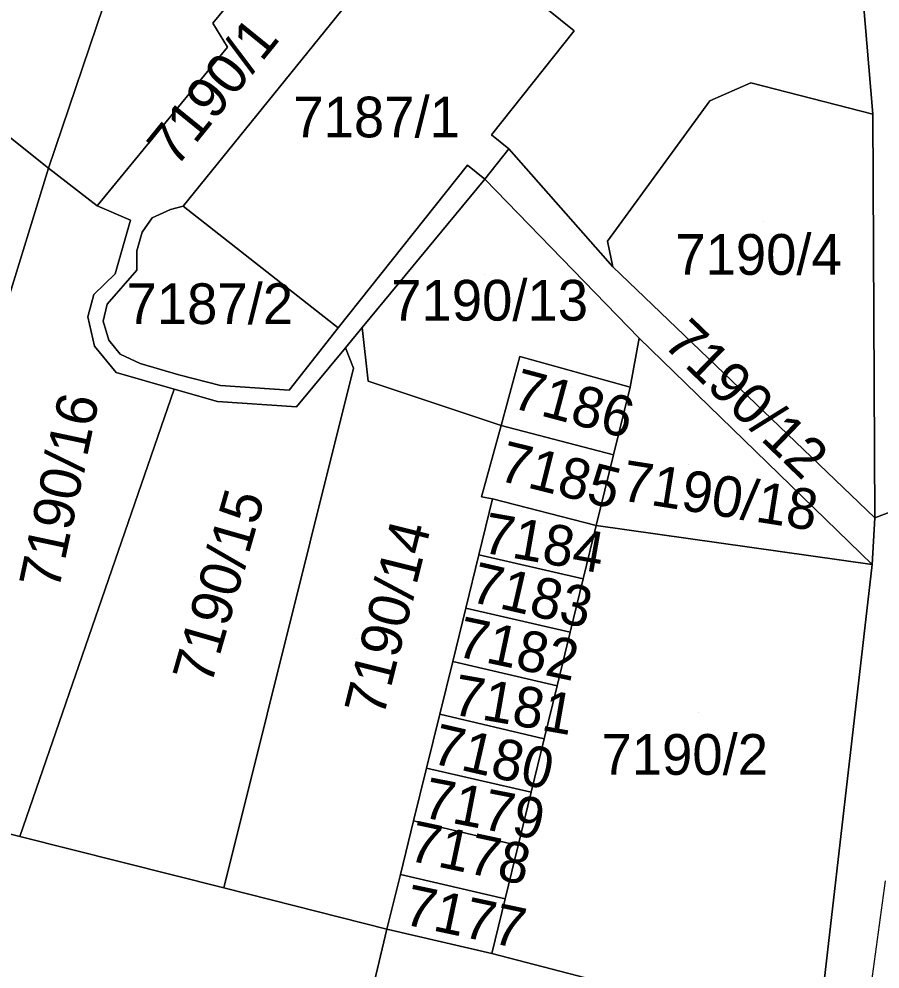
# Model space of a CAD drawing. Extents: x -266199 to -261993, y -1239047 to -1235108.
# Drawn here: x -263537.93 to -263495.63, y -1236309.89 to -1236263.23 of the extents above; entities that cross this region are included whole.
import ezdxf

# ---------------------------------------------------------------- set-up
doc = ezdxf.new("R2010")
doc.units = 0
for name, color, linetype in [('body_kn', 7, 'Continuous'), ('kladpar_druhypozemkov', 7, 'Continuous'), ('kladpar_hranice', 7, 'Continuous'), ('kladpar_parcelnecisla', 7, 'Continuous'), ('kladpar_plochy', 7, 'Continuous'), ('zappar_hrandruhpozemk', 7, 'Continuous')]:
    doc.layers.add(name, color=color, linetype=linetype)

msp = doc.modelspace()

# ---------------------------------------------------------------- linework, layer by layer
at = {"layer": 'body_kn'}
for p, q in [((-263528.41, -1236263.43), (-263528.41, -1236263.43)), ((-263510.66, -1236263.8), (-263510.66, -1236263.8)), ((-263510.66, -1236263.8), (-263510.66, -1236263.8)), ((-263527.69, -1236264.61), (-263527.69, -1236264.61)), ((-263501.98, -1236266.36), (-263501.98, -1236266.36)), ((-263503.99, -1236267.25), (-263503.99, -1236267.25)), ((-263495.99, -1236267.9), (-263495.99, -1236267.9)), ((-263514.72, -1236268.91), (-263514.72, -1236268.91)), ((-263513.86, -1236269.6), (-263513.86, -1236269.6)), ((-263536.48, -1236270.56), (-263536.48, -1236270.56)), ((-263536.48, -1236270.56), (-263536.48, -1236270.56)), ((-263515.9, -1236270.4), (-263515.9, -1236270.4)), ((-263515.04, -1236271.09), (-263515.04, -1236271.09)), ((-263515.04, -1236271.09), (-263515.04, -1236271.09)), ((-263534.09, -1236272.4), (-263534.09, -1236272.4)), ((-263534.09, -1236272.4), (-263534.09, -1236272.4)), ((-263529.86, -1236272.42), (-263529.86, -1236272.42)), ((-263529.86, -1236272.42), (-263529.86, -1236272.42)), ((-263530.49, -1236272.59), (-263530.49, -1236272.59)), ((-263530.49, -1236272.59), (-263530.49, -1236272.59)), ((-263532.45, -1236273.11), (-263532.45, -1236273.11)), ((-263531.39, -1236272.99), (-263531.39, -1236272.99)), ((-263531.87, -1236273.69), (-263531.87, -1236273.69)), ((-263509.02, -1236274.13), (-263509.02, -1236274.13)), ((-263532.14, -1236274.62), (-263532.14, -1236274.62)), ((-263533.2, -1236275.75), (-263533.2, -1236275.75)), ((-263532.14, -1236275.56), (-263532.14, -1236275.56)), ((-263508.76, -1236275.4), (-263508.76, -1236275.4)), ((-263534.25, -1236276.75), (-263534.25, -1236276.75)), ((-263533.6, -1236277.24), (-263533.6, -1236277.24)), ((-263534.55, -1236277.86), (-263534.55, -1236277.86)), ((-263533.79, -1236278.07), (-263533.79, -1236278.07)), ((-263522.24, -1236278.4), (-263522.24, -1236278.4)), ((-263521.07, -1236278.38), (-263521.07, -1236278.38)), ((-263521.07, -1236278.38), (-263521.07, -1236278.38)), ((-263533.52, -1236279), (-263533.52, -1236279)), ((-263507.46, -1236278.91), (-263507.46, -1236278.91)), ((-263534.22, -1236279.3), (-263534.22, -1236279.3)), ((-263521.89, -1236279.37), (-263521.89, -1236279.37)), ((-263521.89, -1236279.37), (-263521.89, -1236279.37)), ((-263532.95, -1236279.69), (-263532.95, -1236279.69)), ((-263513.32, -1236279.8), (-263513.32, -1236279.8)), ((-263531.98, -1236280.14), (-263531.98, -1236280.14)), ((-263521.49, -1236280.38), (-263521.49, -1236280.38)), ((-263533.15, -1236280.59), (-263533.15, -1236280.59)), ((-263530.08, -1236280.71), (-263530.08, -1236280.71)), ((-263528.02, -1236281.22), (-263528.02, -1236281.22)), ((-263520.77, -1236281.02), (-263520.77, -1236281.02)), ((-263507.91, -1236281.31), (-263507.91, -1236281.31)), ((-263530.31, -1236281.4), (-263530.31, -1236281.4)), ((-263530.31, -1236281.4), (-263530.31, -1236281.4)), ((-263524.66, -1236281.45), (-263524.66, -1236281.45)), ((-263528.17, -1236282.01), (-263528.17, -1236282.01)), ((-263524.3, -1236282.28), (-263524.3, -1236282.28)), ((-263514.24, -1236283.19), (-263514.24, -1236283.19)), ((-263514.24, -1236283.19), (-263514.24, -1236283.19)), ((-263508.72, -1236284.64), (-263508.72, -1236284.64)), ((-263515.2, -1236286.69), (-263515.2, -1236286.69)), ((-263514.66, -1236286.8), (-263514.66, -1236286.8)), ((-263514.66, -1236286.8), (-263514.66, -1236286.8)), ((-263495.88, -1236287.73), (-263495.88, -1236287.73)), ((-263495.88, -1236287.73), (-263495.88, -1236287.73)), ((-263509.57, -1236288.11), (-263509.57, -1236288.11)), ((-263509.57, -1236288.11), (-263509.57, -1236288.11)), ((-263515.33, -1236289.55), (-263515.33, -1236289.55)), ((-263515.33, -1236289.55), (-263515.33, -1236289.55)), ((-263496.02, -1236290.02), (-263496.02, -1236290.02)), ((-263496.02, -1236290.02), (-263496.02, -1236290.02)), ((-263510.21, -1236290.73), (-263510.21, -1236290.73)), ((-263515.98, -1236292.17), (-263515.98, -1236292.17)), ((-263515.98, -1236292.17), (-263515.98, -1236292.17)), ((-263510.85, -1236293.35), (-263510.85, -1236293.35)), ((-263516.62, -1236294.79), (-263516.62, -1236294.79)), ((-263516.62, -1236294.79), (-263516.62, -1236294.79)), ((-263511.49, -1236295.98), (-263511.49, -1236295.98)), ((-263517.26, -1236297.38), (-263517.26, -1236297.38)), ((-263517.26, -1236297.38), (-263517.26, -1236297.38)), ((-263512.13, -1236298.59), (-263512.13, -1236298.59)), ((-263517.91, -1236300.02), (-263517.91, -1236300.02)), ((-263517.91, -1236300.02), (-263517.91, -1236300.02)), ((-263512.77, -1236301.21), (-263512.77, -1236301.21)), ((-263518.55, -1236302.62), (-263518.55, -1236302.62)), ((-263518.55, -1236302.62), (-263518.55, -1236302.62)), ((-263537.88, -1236303.38), (-263537.88, -1236303.38)), ((-263513.4, -1236303.82), (-263513.4, -1236303.82)), ((-263519.19, -1236305.25), (-263519.19, -1236305.25)), ((-263519.19, -1236305.25), (-263519.19, -1236305.25)), ((-263527.86, -1236305.91), (-263527.86, -1236305.91)), ((-263514.04, -1236306.44), (-263514.04, -1236306.44)), ((-263519.85, -1236307.93), (-263519.85, -1236307.93)), ((-263519.85, -1236307.93), (-263519.85, -1236307.93)), ((-263514.7, -1236309.13), (-263514.7, -1236309.13))]:
    msp.add_line(p, q, dxfattribs=at)
at = {"layer": 'kladpar_druhypozemkov'}
for p, q in [((-263520.11, -1236266.95), (-263520.11, -1236266.95)), ((-263501.37, -1236273.19), (-263501.37, -1236273.19)), ((-263515.04, -1236275.78), (-263515.04, -1236275.78)), ((-263529.42, -1236276.34), (-263529.42, -1236276.34)), ((-263508.05, -1236277.86), (-263508.05, -1236277.86)), ((-263510.77, -1236281.31), (-263510.77, -1236281.31)), ((-263511.72, -1236284.66), (-263511.72, -1236284.66)), ((-263505.03, -1236285.12), (-263505.03, -1236285.12)), ((-263512.31, -1236288.01), (-263512.31, -1236288.01)), ((-263529.29, -1236290.6), (-263529.29, -1236290.6)), ((-263512.99, -1236290.59), (-263512.99, -1236290.59)), ((-263513.94, -1236293.24), (-263513.94, -1236293.24)), ((-263521.37, -1236293.68), (-263521.37, -1236293.68)), ((-263514.07, -1236295.96), (-263514.07, -1236295.96)), ((-263504.53, -1236297.27), (-263504.53, -1236297.27)), ((-263515.02, -1236298.4), (-263515.02, -1236298.4)), ((-263515.43, -1236301.12), (-263515.43, -1236301.12)), ((-263515.97, -1236303.7), (-263515.97, -1236303.7)), ((-263516.44, -1236306.35), (-263516.44, -1236306.35))]:
    msp.add_line(p, q, dxfattribs=at)
at = {"layer": 'kladpar_hranice'}
for p, q in [((-263509.57, -1236288.11), (-263496.02, -1236290.02)), ((-263496.02, -1236290.02), (-263509.57, -1236288.11))]:
    msp.add_line(p, q, dxfattribs=at)
for points in [[(-263539.64, -1236251.93), (-263532.02, -1236257.4), (-263532.77, -1236259.62), (-263536.48, -1236270.56), (-263556.07, -1236254.9), (-263558.35, -1236253.65), (-263553.41, -1236240.69), (-263550.2, -1236243.03), (-263549.33, -1236243.77), (-263552.3, -1236247.3), (-263550.89, -1236248.39), (-263551.92, -1236249.71), (-263550.96, -1236250.5), (-263553.07, -1236253.02), (-263546.88, -1236258.21), (-263544.72, -1236255.63), (-263543.56, -1236256.61), (-263539.64, -1236251.93)], [(-263510.66, -1236263.8), (-263512.67, -1236262.17), (-263502.28, -1236249.13), (-263499.14, -1236245.39), (-263497.67, -1236252.96), (-263496.66, -1236259.95), (-263495.99, -1236267.9), (-263501.98, -1236266.36), (-263503.99, -1236267.25), (-263509.02, -1236274.13), (-263508.76, -1236275.4), (-263513.86, -1236269.6), (-263514.72, -1236268.91), (-263510.66, -1236263.8)], [(-263534.09, -1236272.4), (-263536.48, -1236270.56), (-263532.77, -1236259.62), (-263532.02, -1236257.4), (-263531.64, -1236257.68), (-263527.4, -1236251.24), (-263521.65, -1236255.27), (-263524.98, -1236259.27), (-263528.41, -1236263.43), (-263527.69, -1236264.61), (-263534.09, -1236272.4)], [(-263536.48, -1236270.56), (-263540.55, -1236283.75), (-263552.05, -1236274.37), (-263547.85, -1236269.28), (-263547.02, -1236270), (-263544.76, -1236267.39), (-263549.56, -1236263.34), (-263552.02, -1236266.32), (-263554.1, -1236264.62), (-263555.1, -1236265.84), (-263556.51, -1236264.69), (-263559.5, -1236268.37), (-263562.84, -1236265.41), (-263558.35, -1236253.65), (-263556.07, -1236254.9), (-263536.48, -1236270.56)], [(-263477.77, -1236255.09), (-263476.89, -1236265.26), (-263476.37, -1236281.32), (-263478.43, -1236281.04), (-263490.86, -1236285.81), (-263494.12, -1236287.05), (-263495.88, -1236287.73), (-263495.99, -1236267.9), (-263496.66, -1236259.95)], [(-263529.86, -1236272.42), (-263521.51, -1236262.08), (-263518.11, -1236257.87), (-263512.67, -1236262.17), (-263510.66, -1236263.8), (-263514.72, -1236268.91), (-263513.86, -1236269.6), (-263515.04, -1236271.09), (-263515.9, -1236270.4), (-263522.24, -1236278.4), (-263529.86, -1236272.42)], [(-263529.86, -1236272.42), (-263530.49, -1236272.59), (-263531.39, -1236272.99), (-263531.87, -1236273.69), (-263532.14, -1236274.62), (-263532.14, -1236275.56), (-263533.6, -1236277.24), (-263533.79, -1236278.07), (-263533.52, -1236279), (-263532.95, -1236279.69), (-263531.98, -1236280.14), (-263530.08, -1236280.71), (-263528.02, -1236281.22), (-263524.66, -1236281.45), (-263522.24, -1236278.4), (-263515.9, -1236270.4), (-263515.04, -1236271.09), (-263521.07, -1236278.38), (-263521.89, -1236279.37), (-263524.3, -1236282.28), (-263528.17, -1236282.01), (-263530.31, -1236281.4), (-263533.15, -1236280.59), (-263534.22, -1236279.3), (-263534.55, -1236277.86), (-263534.25, -1236276.75), (-263533.2, -1236275.75), (-263532.45, -1236273.11), (-263534.09, -1236272.4), (-263527.69, -1236264.61), (-263528.41, -1236263.43), (-263524.98, -1236259.27)], [(-263521.51, -1236262.08), (-263529.86, -1236272.42)], [(-263495.88, -1236287.73), (-263508.76, -1236275.4), (-263509.02, -1236274.13), (-263503.99, -1236267.25), (-263501.98, -1236266.36), (-263495.99, -1236267.9), (-263495.88, -1236287.73)], [(-263495.88, -1236287.73), (-263496.02, -1236290.02), (-263507.46, -1236278.91), (-263515.04, -1236271.09), (-263513.86, -1236269.6), (-263508.76, -1236275.4), (-263495.88, -1236287.73)], [(-263530.31, -1236281.4), (-263537.88, -1236303.38), (-263542.57, -1236302.19), (-263544.64, -1236301.78), (-263543.62, -1236295.6), (-263540.55, -1236283.75), (-263536.48, -1236270.56), (-263534.09, -1236272.4), (-263532.45, -1236273.11), (-263533.2, -1236275.75), (-263534.25, -1236276.75), (-263534.55, -1236277.86), (-263534.22, -1236279.3), (-263533.15, -1236280.59), (-263530.31, -1236281.4)], [(-263515.04, -1236271.09), (-263507.46, -1236278.91), (-263507.91, -1236281.31), (-263513.32, -1236279.8), (-263514.24, -1236283.19), (-263520.77, -1236281.02), (-263521.07, -1236278.38), (-263515.04, -1236271.09)], [(-263530.49, -1236272.59), (-263529.86, -1236272.42), (-263522.24, -1236278.4), (-263524.66, -1236281.45), (-263528.02, -1236281.22), (-263530.08, -1236280.71), (-263531.98, -1236280.14), (-263532.95, -1236279.69), (-263533.52, -1236279), (-263533.79, -1236278.07), (-263533.6, -1236277.24), (-263532.14, -1236275.56), (-263532.14, -1236274.62), (-263531.87, -1236273.69), (-263531.39, -1236272.99), (-263530.49, -1236272.59)], [(-263521.07, -1236278.38), (-263520.77, -1236281.02), (-263514.24, -1236283.19), (-263515.2, -1236286.69), (-263514.66, -1236286.8), (-263515.33, -1236289.55), (-263515.98, -1236292.17), (-263516.62, -1236294.79), (-263517.26, -1236297.38), (-263517.91, -1236300.02), (-263518.55, -1236302.62), (-263519.19, -1236305.25), (-263519.85, -1236307.93), (-263527.86, -1236305.91), (-263521.49, -1236280.38), (-263521.89, -1236279.37), (-263521.07, -1236278.38)], [(-263509.57, -1236288.11), (-263508.72, -1236284.64), (-263507.91, -1236281.31), (-263507.46, -1236278.91), (-263496.02, -1236290.02)], [(-263521.89, -1236279.37), (-263521.49, -1236280.38), (-263527.86, -1236305.91), (-263537.88, -1236303.38), (-263530.31, -1236281.4), (-263528.17, -1236282.01), (-263524.3, -1236282.28), (-263521.89, -1236279.37)], [(-263514.24, -1236283.19), (-263513.32, -1236279.8), (-263507.91, -1236281.31), (-263508.72, -1236284.64), (-263514.24, -1236283.19)], [(-263514.66, -1236286.8), (-263515.2, -1236286.69), (-263514.24, -1236283.19), (-263508.72, -1236284.64), (-263509.57, -1236288.11), (-263514.66, -1236286.8)], [(-263515.33, -1236289.55), (-263514.66, -1236286.8), (-263509.57, -1236288.11), (-263510.21, -1236290.73), (-263515.33, -1236289.55)], [(-263525.44, -1236474.41), (-263524.5, -1236462.92), (-263523.93, -1236453.44), (-263523.75, -1236451.12), (-263522.55, -1236433.53), (-263521.18, -1236415.65), (-263521.04, -1236413.78), (-263520.43, -1236405.08), (-263519.44, -1236396.11), (-263519.14, -1236394.44), (-263517.1, -1236385.05), (-263515.04, -1236377.26), (-263514.6, -1236375.57), (-263509.96, -1236360.29), (-263509.29, -1236358.46), (-263506.63, -1236349.88), (-263504.29, -1236342.02), (-263503.67, -1236339.99), (-263501.92, -1236332.7), (-263499.85, -1236322.85), (-263499.54, -1236320.58), (-263496.02, -1236290.02), (-263495.88, -1236287.73), (-263494.12, -1236287.05)], [(-263496.02, -1236290.02), (-263499.54, -1236320.58), (-263509.42, -1236318.4), (-263510.68, -1236318.12), (-263508.83, -1236310.65), (-263514.7, -1236309.13), (-263514.04, -1236306.44), (-263513.4, -1236303.82), (-263512.77, -1236301.21), (-263512.13, -1236298.59), (-263511.49, -1236295.98), (-263510.85, -1236293.35), (-263510.21, -1236290.73), (-263509.57, -1236288.11)], [(-263515.98, -1236292.17), (-263515.33, -1236289.55), (-263510.21, -1236290.73), (-263510.85, -1236293.35), (-263515.98, -1236292.17)], [(-263516.62, -1236294.79), (-263515.98, -1236292.17), (-263510.85, -1236293.35), (-263511.49, -1236295.98), (-263516.62, -1236294.79)], [(-263517.26, -1236297.38), (-263516.62, -1236294.79), (-263511.49, -1236295.98), (-263512.13, -1236298.59), (-263517.26, -1236297.38)], [(-263517.91, -1236300.02), (-263517.26, -1236297.38), (-263512.13, -1236298.59), (-263512.77, -1236301.21), (-263517.91, -1236300.02)], [(-263518.55, -1236302.62), (-263517.91, -1236300.02), (-263512.77, -1236301.21), (-263513.4, -1236303.82), (-263518.55, -1236302.62)], [(-263548.98, -1236348.65), (-263546.75, -1236329.72), (-263543.91, -1236310.97), (-263542.57, -1236302.19), (-263537.88, -1236303.38), (-263527.86, -1236305.91), (-263519.85, -1236307.93), (-263521.69, -1236315.66), (-263522.6, -1236315.39), (-263523.06, -1236317.17), (-263522.12, -1236317.39), (-263523.87, -1236324.22), (-263526.33, -1236334.35), (-263527.51, -1236334.03), (-263527.95, -1236335.81), (-263526.76, -1236336.08), (-263528.55, -1236343.15), (-263530.96, -1236352.97)], [(-263519.19, -1236305.25), (-263518.55, -1236302.62), (-263513.4, -1236303.82), (-263514.04, -1236306.44), (-263519.19, -1236305.25)], [(-263519.85, -1236307.93), (-263519.19, -1236305.25), (-263514.04, -1236306.44), (-263514.7, -1236309.13), (-263519.85, -1236307.93)], [(-263523.87, -1236324.22), (-263522.12, -1236317.39), (-263523.06, -1236317.17), (-263522.6, -1236315.39), (-263521.69, -1236315.66), (-263519.85, -1236307.93), (-263514.7, -1236309.13), (-263508.83, -1236310.65), (-263510.68, -1236318.12), (-263509.42, -1236318.4), (-263509.94, -1236320.65), (-263511.24, -1236320.37), (-263512.87, -1236326.95)]]:
    msp.add_lwpolyline(points, dxfattribs=at)
at = {"layer": 'kladpar_plochy'}
for p, q in [((-263542.57, -1236302.19), (-263537.88, -1236303.38)), ((-263537.88, -1236303.38), (-263527.86, -1236305.91)), ((-263527.86, -1236305.91), (-263519.85, -1236307.93)), ((-263519.85, -1236307.93), (-263521.69, -1236315.66))]:
    msp.add_line(p, q, dxfattribs=at)
for points in [[(-263539.64, -1236251.93), (-263532.02, -1236257.4), (-263532.77, -1236259.62), (-263536.48, -1236270.56), (-263556.07, -1236254.9), (-263558.35, -1236253.65), (-263553.41, -1236240.69), (-263550.2, -1236243.03), (-263549.33, -1236243.77), (-263552.3, -1236247.3), (-263550.89, -1236248.39), (-263551.92, -1236249.71), (-263550.96, -1236250.5), (-263553.07, -1236253.02), (-263546.88, -1236258.21), (-263544.72, -1236255.63), (-263543.56, -1236256.61)], [(-263510.66, -1236263.8), (-263512.67, -1236262.17), (-263502.28, -1236249.13), (-263499.14, -1236245.39), (-263497.67, -1236252.96), (-263496.66, -1236259.95), (-263495.99, -1236267.9), (-263501.98, -1236266.36), (-263503.99, -1236267.25), (-263509.02, -1236274.13), (-263508.76, -1236275.4), (-263513.86, -1236269.6), (-263514.72, -1236268.91)], [(-263534.09, -1236272.4), (-263536.48, -1236270.56), (-263532.77, -1236259.62), (-263532.02, -1236257.4), (-263531.64, -1236257.68), (-263527.4, -1236251.24), (-263521.65, -1236255.27), (-263524.98, -1236259.27), (-263528.41, -1236263.43), (-263527.69, -1236264.61)], [(-263536.48, -1236270.56), (-263540.55, -1236283.75), (-263552.05, -1236274.37), (-263547.85, -1236269.28), (-263547.02, -1236270), (-263544.76, -1236267.39), (-263549.56, -1236263.34), (-263552.02, -1236266.32), (-263554.1, -1236264.62), (-263555.1, -1236265.84), (-263556.51, -1236264.69), (-263559.5, -1236268.37), (-263562.84, -1236265.41), (-263558.35, -1236253.65), (-263556.07, -1236254.9)], [(-263529.86, -1236272.42), (-263521.51, -1236262.08), (-263518.11, -1236257.87), (-263512.67, -1236262.17), (-263510.66, -1236263.8), (-263514.72, -1236268.91), (-263513.86, -1236269.6), (-263515.04, -1236271.09), (-263515.9, -1236270.4), (-263522.24, -1236278.4)], [(-263495.88, -1236287.73), (-263508.76, -1236275.4), (-263509.02, -1236274.13), (-263503.99, -1236267.25), (-263501.98, -1236266.36), (-263495.99, -1236267.9)], [(-263495.88, -1236287.73), (-263496.02, -1236290.02), (-263507.46, -1236278.91), (-263515.04, -1236271.09), (-263513.86, -1236269.6), (-263508.76, -1236275.4)], [(-263530.31, -1236281.4), (-263537.88, -1236303.38), (-263542.57, -1236302.19), (-263544.64, -1236301.78), (-263543.62, -1236295.6), (-263540.55, -1236283.75), (-263536.48, -1236270.56), (-263534.09, -1236272.4), (-263532.45, -1236273.11), (-263533.2, -1236275.75), (-263534.25, -1236276.75), (-263534.55, -1236277.86), (-263534.22, -1236279.3), (-263533.15, -1236280.59)], [(-263515.04, -1236271.09), (-263507.46, -1236278.91), (-263507.91, -1236281.31), (-263513.32, -1236279.8), (-263514.24, -1236283.19), (-263520.77, -1236281.02), (-263521.07, -1236278.38)], [(-263530.49, -1236272.59), (-263529.86, -1236272.42), (-263522.24, -1236278.4), (-263524.66, -1236281.45), (-263528.02, -1236281.22), (-263530.08, -1236280.71), (-263531.98, -1236280.14), (-263532.95, -1236279.69), (-263533.52, -1236279), (-263533.79, -1236278.07), (-263533.6, -1236277.24), (-263532.14, -1236275.56), (-263532.14, -1236274.62), (-263531.87, -1236273.69), (-263531.39, -1236272.99)], [(-263521.07, -1236278.38), (-263520.77, -1236281.02), (-263514.24, -1236283.19), (-263515.2, -1236286.69), (-263514.66, -1236286.8), (-263515.33, -1236289.55), (-263515.98, -1236292.17), (-263516.62, -1236294.79), (-263517.26, -1236297.38), (-263517.91, -1236300.02), (-263518.55, -1236302.62), (-263519.19, -1236305.25), (-263519.85, -1236307.93), (-263527.86, -1236305.91), (-263521.49, -1236280.38), (-263521.89, -1236279.37)], [(-263496.02, -1236290.02), (-263509.57, -1236288.11), (-263508.72, -1236284.64), (-263507.91, -1236281.31), (-263507.46, -1236278.91)], [(-263521.89, -1236279.37), (-263521.49, -1236280.38), (-263527.86, -1236305.91), (-263537.88, -1236303.38), (-263530.31, -1236281.4), (-263528.17, -1236282.01), (-263524.3, -1236282.28)], [(-263514.24, -1236283.19), (-263513.32, -1236279.8), (-263507.91, -1236281.31), (-263508.72, -1236284.64)], [(-263514.66, -1236286.8), (-263515.2, -1236286.69), (-263514.24, -1236283.19), (-263508.72, -1236284.64), (-263509.57, -1236288.11)], [(-263515.33, -1236289.55), (-263514.66, -1236286.8), (-263509.57, -1236288.11), (-263510.21, -1236290.73)], [(-263509.57, -1236288.11), (-263496.02, -1236290.02), (-263499.54, -1236320.58), (-263509.42, -1236318.4), (-263510.68, -1236318.12), (-263508.83, -1236310.65), (-263514.7, -1236309.13), (-263514.04, -1236306.44), (-263513.4, -1236303.82), (-263512.77, -1236301.21), (-263512.13, -1236298.59), (-263511.49, -1236295.98), (-263510.85, -1236293.35), (-263510.21, -1236290.73)], [(-263515.98, -1236292.17), (-263515.33, -1236289.55), (-263510.21, -1236290.73), (-263510.85, -1236293.35)], [(-263516.62, -1236294.79), (-263515.98, -1236292.17), (-263510.85, -1236293.35), (-263511.49, -1236295.98)], [(-263517.26, -1236297.38), (-263516.62, -1236294.79), (-263511.49, -1236295.98), (-263512.13, -1236298.59)], [(-263517.91, -1236300.02), (-263517.26, -1236297.38), (-263512.13, -1236298.59), (-263512.77, -1236301.21)], [(-263518.55, -1236302.62), (-263517.91, -1236300.02), (-263512.77, -1236301.21), (-263513.4, -1236303.82)], [(-263519.19, -1236305.25), (-263518.55, -1236302.62), (-263513.4, -1236303.82), (-263514.04, -1236306.44)], [(-263519.85, -1236307.93), (-263519.19, -1236305.25), (-263514.04, -1236306.44), (-263514.7, -1236309.13)], [(-263523.87, -1236324.22), (-263522.12, -1236317.39), (-263523.06, -1236317.17), (-263522.6, -1236315.39), (-263521.69, -1236315.66), (-263519.85, -1236307.93), (-263514.7, -1236309.13), (-263508.83, -1236310.65), (-263510.68, -1236318.12), (-263509.42, -1236318.4), (-263509.94, -1236320.65), (-263511.24, -1236320.37), (-263512.87, -1236326.95)]]:
    msp.add_lwpolyline(points, close=True, dxfattribs=at)
for points in [[(-263477.77, -1236255.09), (-263476.89, -1236265.26), (-263476.37, -1236281.32), (-263478.43, -1236281.04), (-263490.86, -1236285.81), (-263494.12, -1236287.05), (-263495.88, -1236287.73), (-263495.99, -1236267.9), (-263496.66, -1236259.95)], [(-263521.51, -1236262.08), (-263529.86, -1236272.42), (-263530.49, -1236272.59), (-263531.39, -1236272.99), (-263531.87, -1236273.69), (-263532.14, -1236274.62), (-263532.14, -1236275.56), (-263533.6, -1236277.24), (-263533.79, -1236278.07), (-263533.52, -1236279), (-263532.95, -1236279.69), (-263531.98, -1236280.14), (-263530.08, -1236280.71), (-263528.02, -1236281.22), (-263524.66, -1236281.45), (-263522.24, -1236278.4), (-263515.9, -1236270.4), (-263515.04, -1236271.09), (-263521.07, -1236278.38), (-263521.89, -1236279.37), (-263524.3, -1236282.28), (-263528.17, -1236282.01), (-263530.31, -1236281.4), (-263533.15, -1236280.59), (-263534.22, -1236279.3), (-263534.55, -1236277.86), (-263534.25, -1236276.75), (-263533.2, -1236275.75), (-263532.45, -1236273.11), (-263534.09, -1236272.4), (-263527.69, -1236264.61), (-263528.41, -1236263.43), (-263524.98, -1236259.27)], [(-263525.44, -1236474.41), (-263524.5, -1236462.92), (-263523.93, -1236453.44), (-263523.75, -1236451.12), (-263522.55, -1236433.53), (-263521.18, -1236415.65), (-263521.04, -1236413.78), (-263520.43, -1236405.08), (-263519.44, -1236396.11), (-263519.14, -1236394.44), (-263517.1, -1236385.05), (-263515.04, -1236377.26), (-263514.6, -1236375.57), (-263509.96, -1236360.29), (-263509.29, -1236358.46), (-263506.63, -1236349.88), (-263504.29, -1236342.02), (-263503.67, -1236339.99), (-263501.92, -1236332.7), (-263499.85, -1236322.85), (-263499.54, -1236320.58), (-263496.02, -1236290.02), (-263495.88, -1236287.73), (-263494.12, -1236287.05)]]:
    msp.add_lwpolyline(points, dxfattribs=at)
at = {"layer": 'zappar_hrandruhpozemk'}
msp.add_line((-263495.38, -1236305.56), (-263497.46, -1236320.81), dxfattribs=at)

# ---------------------------------------------------------------- texts
at = {"layer": 'kladpar_parcelnecisla'}
for s, rotation, p in [('7190/1', 51, (-263530.22, -1236270.58)), ('7190/12', 316, (-263506.359, -1236279.227)), ('7186', 345, (-263513.802, -1236282.301)), ('7190/16', 78, (-263535.985, -1236291.339)), ('7185', 346, (-263514.46, -1236285.867)), ('7190/18', 351, (-263508.417, -1236286.859)), ('7190/15', 74, (-263528.494, -1236296.008)), ('7184', 350, (-263515.238, -1236289.419)), ('7190/14', 76, (-263520.027, -1236297.575)), ('7183', 347, (-263515.841, -1236291.827)), ('7182', 348, (-263516.519, -1236294.512)), ('7181', 350, (-263516.714, -1236297.37)), ('7180', 347, (-263517.742, -1236299.763)), ('7179', 349, (-263518.179, -1236302.424)), ('7178', 348, (-263518.88, -1236304.541)), ('7177', 348, (-263519.111, -1236307.676))]:
    msp.add_text(s, height=2, rotation=rotation, dxfattribs=at).set_placement(p)
for s, p in [('7187/1', (-263524.448, -1236269.04)), ('7190/4', (-263505.685, -1236275.79)), ('7187/2', (-263532.644, -1236278.21)), ('7190/13', (-263519.639, -1236278.04)), ('7190/2', (-263509.311, -1236300.35))]:
    msp.add_text(s, height=2, dxfattribs=at).set_placement(p)

doc.saveas('drawing.dxf')
